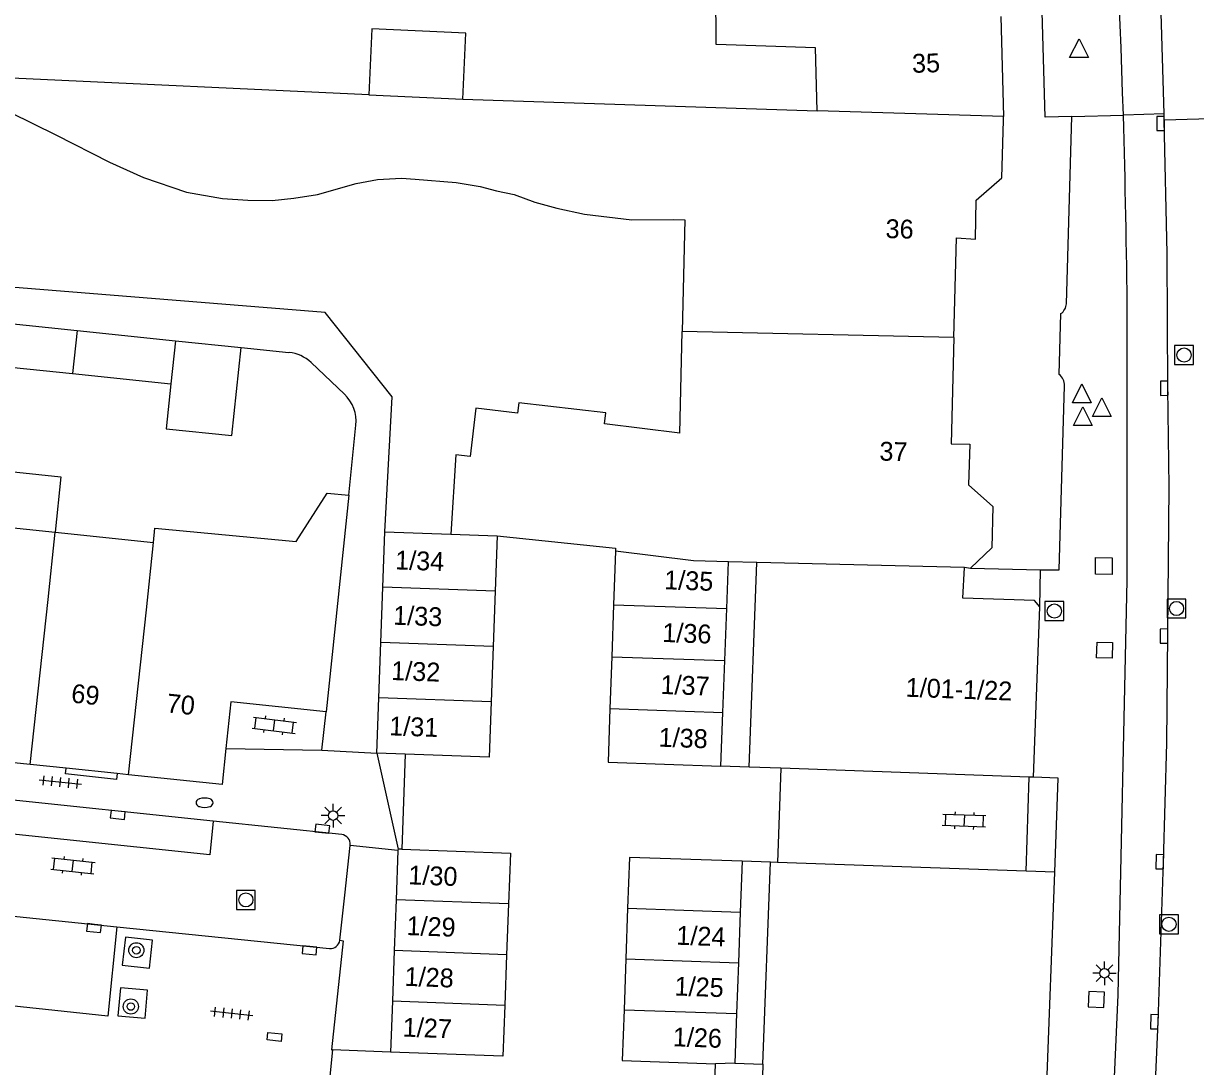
# Model space of a CAD drawing. Extents: x 132998 to 136004, y 396998 to 398512.
# Drawn here: x 133481.2 to 133543.5, y 397360.2 to 397415.5 of the extents above; entities that cross this region are included whole.
import ezdxf

# ---------------------------------------------------------------- set-up
doc = ezdxf.new("R2010")
doc.units = 0
for name, color, linetype in [('gg-afsc-erfafscheiding', 7, 'Continuous'), ('gg-afsc-hekwerk', 7, 'Continuous'), ('gg-afsc-muur', 7, 'Continuous'), ('gg-anno-huisnummerreeks BGT', 7, 'Continuous'), ('gg-bbg-bijgebouw', 7, 'Continuous'), ('gg-bbg-gedigitaliseerde bebouwing', 7, 'Continuous'), ('gg-bbg-gedigitaliseerde bijgebouw', 7, 'Continuous'), ('gg-bbg-hoofdgebouw', 7, 'Continuous'), ('gg-bbg-luifel en loopbrug', 7, 'Continuous'), ('gg-bbg-onder overbouw', 7, 'Continuous'), ('gg-bbg-pand overbouw', 7, 'Continuous'), ('gg-bbg-tussenscheiding', 7, 'Continuous'), ('gg-knt-verharding', 7, 'Continuous'), ('gg-knt-verharding nz', 7, 'Continuous'), ('gt-grn-weggrens', 7, 'Continuous'), ('gt-symb-boom', 7, 'Continuous'), ('gt-symb-brandkraan', 7, 'Continuous'), ('gt-symb-klinker verharding', 7, 'Continuous'), ('gt-symb-kolk', 7, 'Continuous'), ('gt-symb-kolk center center', 7, 'Continuous'), ('gt-symb-lichtmast', 7, 'Continuous'), ('gt-symb-rioolschacht', 7, 'Continuous'), ('gt-symb-tegel verharding', 7, 'Continuous'), ('gt-symb-waterafsluiter', 7, 'Continuous')]:
    doc.layers.add(name, color=color, linetype=linetype)

# ---------------------------------------------------------------- blocks, each defined once
blk = doc.blocks.new('gt0-KOLK')
at = {"layer": 'gt-symb-kolk'}
blk.add_lwpolyline([(0, 0), (0.375, 0), (0.375, 0.4), (-0.375, 0.4), (-0.375, 0), (0, 0)], dxfattribs=at)
blk = doc.blocks.new('gt0-WAFSL')
at = {"layer": 'gt-symb-waterafsluiter'}
for p, q in [((-0.5, -0.333), (0, 0.667)), ((0, 0.667), (0.5, -0.333)), ((0.5, -0.333), (-0.5, -0.333))]:
    blk.add_line(p, q, dxfattribs=at)
blk = doc.blocks.new('gt0-RS')
at = {"layer": 'gt-symb-rioolschacht'}
blk.add_lwpolyline([(-0.5, -0.5), (0.5, -0.5), (0.5, 0.5), (-0.5, 0.5)], close=True, dxfattribs=at)
blk.add_circle((0, 0), 0.375, dxfattribs=at)
blk = doc.blocks.new('gt0-TEG1')
at = {"layer": 'gt-symb-tegel verharding'}
for p, q in [((-1.125, 0), (1.125, 0)), ((-0.9, -0.25), (-0.9, 0.25)), ((-0.45, -0.25), (-0.45, 0.25)), ((0, -0.25), (0, 0.25)), ((0.45, -0.25), (0.45, 0.25)), ((0.9, -0.25), (0.9, 0.25))]:
    blk.add_line(p, q, dxfattribs=at)
blk = doc.blocks.new('gt0-KL1')
at = {"layer": 'gt-symb-klinker verharding'}
for p, q in [((-1.15, 0.3), (1.15, 0.3)), ((-1, -0.3), (-1, 0.3)), ((-0.5, 0.3), (-0.5, 0.45)), ((0, -0.3), (0, 0.3)), ((0.5, 0.3), (0.5, 0.45)), ((1, -0.3), (1, 0.3)), ((-1.15, -0.3), (1.15, -0.3)), ((-0.5, -0.45), (-0.5, -0.3)), ((0.5, -0.45), (0.5, -0.3))]:
    blk.add_line(p, q, dxfattribs=at)
blk = doc.blocks.new('gt0-LMAST')
at = {"layer": 'gt-symb-lichtmast'}
for p, q in [((-0.182, 0.173), (-0.447, 0.438)), ((-0.005, 0.246), (-0.005, 0.621)), ((0.172, 0.173), (0.437, 0.438)), ((-0.255, -0.004), (-0.63, -0.004)), ((-0.182, -0.181), (-0.447, -0.446)), ((-0.005, -0.254), (-0.005, -0.629)), ((0.437, -0.446), (0.172, -0.181)), ((0.245, -0.004), (0.62, -0.004))]:
    blk.add_line(p, q, dxfattribs=at)
blk.add_circle((-0.005, -0.004), 0.25, dxfattribs=at)
blk = doc.blocks.new('gt0-BOOM')
at = {"layer": 'gt-symb-boom'}
for radius in [0.4, 0.2]:
    blk.add_circle((0, 0), radius, dxfattribs=at)
blk = doc.blocks.new('gt0-BR')
at = {"layer": 'gt-symb-brandkraan'}
for centre, radius, start, end in [((-0.244, 0), 0.206, 107.56694, 252.43307), ((0.599, -2.664), 3, 106.89205, 107.56694), ((0, -0.691), 0.938, 73.10799, 106.89205), ((-0.599, -2.664), 3, 72.43309, 73.10799), ((0.244, 0), 0.206, 287.56695, 72.43309), ((0.599, 2.664), 3, 252.43307, 253.10797), ((0, 0.691), 0.938, 253.10797, 286.89206), ((-0.599, 2.664), 3, 286.89206, 287.56695)]:
    blk.add_arc(centre, radius, start, end, dxfattribs=at)
blk = doc.blocks.new('gt0-KOLKCC')
at = {"layer": 'gt-symb-kolk center center'}
blk.add_lwpolyline([(-0.375, 0.2), (0.375, 0.2), (0.375, -0.2), (-0.375, -0.2)], close=True, dxfattribs=at)

msp = doc.modelspace()

# ---------------------------------------------------------------- linework, layer by layer
at = {"layer": 'gg-afsc-erfafscheiding'}
for p, q in [((133492.798, 397398.327), (133495.342, 397398.064)), ((133496.512, 397397.527), (133498.279, 397395.853)), ((133498.509, 397390.484), (133498.893, 397394.195))]:
    msp.add_line(p, q, dxfattribs=at)
msp.add_lwpolyline([(133500.42, 397388.55), (133500.823, 397395.703), (133497.267, 397400.181), (133454.225, 397403.644), (133455.323, 397421.968), (133456.396, 397429.5), (133457.85, 397437.75)], dxfattribs=at)
for centre, radius, start, end in [((133495.138, 397396.076), 1.999, 46.56082, 84.13136), ((133496.901, 397394.4), 2.003, 354.12984, 46.51193)]:
    msp.add_arc(centre, radius, start, end, dxfattribs=at)
at = {"layer": 'gg-afsc-hekwerk'}
for p, q in [((133500, 397376.8), (133501.13, 397371.71)), ((133519.765, 397376.058), (133518.263, 397376.103)), ((133520.893, 397371.013), (133519.391, 397371.068))]:
    msp.add_line(p, q, dxfattribs=at)
at = {"layer": 'gg-afsc-muur'}
for p, q in [((133497.65, 397361.05), (133497.362, 397358.239)), ((133500.73, 397360.93), (133497.65, 397361.05))]:
    msp.add_line(p, q, dxfattribs=at)
at = {"layer": 'gg-bbg-bijgebouw'}
for p, q in [((133500.315, 397385.602), (133500.42, 397388.55)), ((133506.39, 397388.33), (133506.285, 397385.395)), ((133512.672, 397387.513), (133512.571, 397384.677)), ((133500.21, 397382.667), (133500.315, 397385.602)), ((133506.285, 397385.395), (133506.18, 397382.46)), ((133512.571, 397384.677), (133512.474, 397381.919)), ((133500.105, 397379.732), (133500.21, 397382.667)), ((133506.18, 397382.46), (133506.075, 397379.525)), ((133512.474, 397381.919), (133512.376, 397379.161)), ((133500, 397376.8), (133500.105, 397379.732)), ((133501.506, 397376.747), (133500, 397376.8)), ((133501.127, 397371.63), (133501.03, 397369.017)), ((133501.13, 397371.71), (133501.127, 397371.63)), ((133501.33, 397371.703), (133501.13, 397371.71)), ((133501.03, 397369.017), (133500.93, 397366.325)), ((133506.99, 397368.798), (133506.89, 397366.105)), ((133513.312, 397368.577), (133513.218, 397365.883)), ((133500.93, 397366.325), (133500.83, 397363.632)), ((133506.89, 397366.105), (133506.79, 397363.413)), ((133513.218, 397365.883), (133513.124, 397363.189)), ((133500.83, 397363.632), (133500.73, 397360.93)), ((133517.843, 397356.426), (133517.978, 397360.323))]:
    msp.add_line(p, q, dxfattribs=at)
for points in [[(133506.075, 397379.525), (133505.97, 397376.59), (133501.506, 397376.747)], [(133512.376, 397379.161), (133512.275, 397376.324), (133518.263, 397376.103)], [(133501.33, 397371.703), (133507.09, 397371.49), (133506.99, 397368.798)], [(133519.391, 397371.068), (133513.405, 397371.271), (133513.312, 397368.577)], [(133506.79, 397363.413), (133506.69, 397360.72), (133500.73, 397360.93)], [(133513.124, 397363.189), (133513.031, 397360.495), (133517.978, 397360.323)]]:
    msp.add_lwpolyline(points, dxfattribs=at)
at = {"layer": 'gg-bbg-gedigitaliseerde bebouwing'}
for p, q in [((133504.57, 397411.507), (133523.367, 397410.88)), ((133516.077, 397393.782), (133516.211, 397399.18)), ((133498.509, 397390.484), (133497.32, 397378.99)), ((133477.89, 397389.047), (133482.929, 397388.526)), ((133482.929, 397388.526), (133488.15, 397387.986)), ((133520.166, 397386.918), (133518.664, 397386.955)), ((133519.765, 397376.058), (133520.166, 397386.918)), ((133520.496, 397360.29), (133520.893, 397371.013))]:
    msp.add_line(p, q, dxfattribs=at)
for points in [[(133523.367, 397410.88), (133523.286, 397414.223), (133518.008, 397414.406), (133517.993, 397417.308), (133523.438, 397417.532)], [(133499.575, 397411.74), (133480.641, 397412.623)], [(133480.556, 397410.786), (133482.967, 397409.607), (133485.824, 397408.155), (133487.628, 397407.341), (133489.907, 397406.568), (133491.813, 397406.224), (133493.15, 397406.14), (133494.445, 397406.131), (133495.595, 397406.25), (133496.848, 397406.436), (133498.906, 397407.019), (133500.036, 397407.247), (133501.314, 397407.301), (133502.04, 397407.261), (133504.206, 397407.073), (133505.491, 397406.869), (133506.362, 397406.642), (133507.299, 397406.441), (133508.385, 397406.039), (133509.563, 397405.718), (133511.024, 397405.397), (133513.529, 397405.102), (133515.732, 397405.109), (133516.357, 397405.094), (133516.211, 397399.18)], [(133516.077, 397393.782), (133512.08, 397394.271), (133512.157, 397394.859), (133507.54, 397395.382), (133507.475, 397394.834), (133505.251, 397395.106), (133504.962, 397392.545), (133504.196, 397392.632), (133503.933, 397388.421)], [(133488.15, 397387.986), (133488.227, 397388.73), (133495.731, 397388.038), (133497.36, 397390.588), (133498.509, 397390.484)]]:
    msp.add_lwpolyline(points, dxfattribs=at)
at = {"layer": 'gg-bbg-gedigitaliseerde bijgebouw'}
for p, q in [((133479.048, 397399.749), (133484.105, 397399.226)), ((133484.105, 397399.226), (133489.325, 397398.686)), ((133489.325, 397398.686), (133492.798, 397398.327)), ((133478.796, 397397.463), (133483.853, 397396.94)), ((133483.853, 397396.94), (133489.073, 397396.4)), ((133500.42, 397388.55), (133503.933, 397388.421)), ((133518.572, 397384.468), (133518.664, 397386.955)), ((133518.47, 397381.711), (133518.572, 397384.468)), ((133518.368, 397378.953), (133518.47, 397381.711)), ((133518.263, 397376.103), (133518.368, 397378.953)), ((133519.391, 397371.068), (133519.292, 397368.369)), ((133519.292, 397368.369), (133519.193, 397365.676)), ((133519.193, 397365.676), (133519.095, 397362.982)), ((133519.095, 397362.982), (133518.998, 397360.345)), ((133518.998, 397360.345), (133520.496, 397360.29))]:
    msp.add_line(p, q, dxfattribs=at)
for points in [[(133504.57, 397411.507), (133504.733, 397415.003), (133499.738, 397415.236), (133499.575, 397411.74)], [(133489.073, 397396.4), (133488.827, 397394.016), (133492.316, 397393.656), (133492.798, 397398.327)]]:
    msp.add_lwpolyline(points, dxfattribs=at)
at = {"layer": 'gg-bbg-hoofdgebouw'}
for p, q in [((133533.125, 397415.891), (133533.255, 397410.574)), ((133534.86, 397375.52), (133535.19, 397384.57)), ((133481.608, 397376.194), (133476.551, 397376.717)), ((133483.511, 397375.997), (133481.608, 397376.194)), ((133486.224, 397375.717), (133483.511, 397375.997)), ((133486.829, 397375.654), (133486.224, 397375.717)), ((133521.451, 397375.998), (133519.765, 397376.058)), ((133534.86, 397375.52), (133534.633, 397375.528)), ((133521.274, 397371), (133520.893, 397371.013)), ((133535.98, 397370.48), (133534.467, 397370.533)), ((133535.533, 397358.556), (133535.98, 397370.48))]:
    msp.add_line(p, q, dxfattribs=at)
for points in [[(133530.629, 397398.855), (133530.76, 397404.14), (133531.77, 397404.07), (133531.82, 397406.15), (133533.18, 397407.32), (133533.26, 397410.38), (133533.255, 397410.574)], [(133530.629, 397398.855), (133530.49, 397393.21), (133531.47, 397393.19), (133531.41, 397391.03), (133532.69, 397389.88), (133532.64, 397387.7), (133531.51, 397386.62)], [(133506.39, 397388.33), (133512.678, 397387.671), (133512.672, 397387.513)], [(133535.19, 397384.57), (133534.9, 397384.9), (133531.1, 397385.03), (133531.189, 397386.644)], [(133531.189, 397386.644), (133531.19, 397386.66), (133531.51, 397386.62)], [(133497.32, 397378.99), (133492.25, 397379.53), (133491.996, 397377.049)], [(133491.996, 397377.049), (133491.8, 397375.14), (133486.829, 397375.654)]]:
    msp.add_lwpolyline(points, dxfattribs=at)
at = {"layer": 'gg-bbg-luifel en loopbrug'}
msp.add_lwpolyline([(133477.89, 397389.047), (133478.209, 397391.984), (133483.241, 397391.464), (133482.929, 397388.526)], dxfattribs=at)
at = {"layer": 'gg-bbg-onder overbouw'}
for p, q in [((133534.633, 397375.528), (133521.451, 397375.998)), ((133534.467, 397370.533), (133521.274, 397371))]:
    msp.add_line(p, q, dxfattribs=at)
at = {"layer": 'gg-bbg-pand overbouw'}
for p, q in [((133521.451, 397375.998), (133521.274, 397371)), ((133534.467, 397370.533), (133534.633, 397375.528))]:
    msp.add_line(p, q, dxfattribs=at)
at = {"layer": 'gg-bbg-tussenscheiding'}
for p, q in [((133499.575, 397411.74), (133504.57, 397411.507)), ((133533.255, 397410.574), (133523.367, 397410.88)), ((133484.105, 397399.226), (133483.853, 397396.94)), ((133489.325, 397398.686), (133489.073, 397396.4)), ((133530.629, 397398.855), (133516.211, 397399.18)), ((133503.933, 397388.421), (133506.39, 397388.33)), ((133531.189, 397386.644), (133520.166, 397386.918)), ((133506.285, 397385.395), (133500.315, 397385.602)), ((133512.571, 397384.677), (133518.572, 397384.468)), ((133506.18, 397382.46), (133500.21, 397382.667)), ((133512.474, 397381.919), (133518.47, 397381.711)), ((133506.075, 397379.525), (133500.105, 397379.732)), ((133512.376, 397379.161), (133518.368, 397378.953)), ((133506.99, 397368.798), (133501.03, 397369.017)), ((133513.312, 397368.577), (133519.292, 397368.369)), ((133506.89, 397366.105), (133500.93, 397366.325)), ((133513.218, 397365.883), (133519.193, 397365.676)), ((133506.79, 397363.413), (133500.83, 397363.632)), ((133513.124, 397363.189), (133519.095, 397362.982)), ((133518.998, 397360.345), (133517.978, 397360.323)), ((133520.496, 397360.29), (133520.475, 397359.636))]:
    msp.add_line(p, q, dxfattribs=at)
for points in [[(133481.608, 397376.194), (133482.559, 397384.952), (133482.929, 397388.526)], [(133486.829, 397375.654), (133487.78, 397384.411), (133488.15, 397387.986)], [(133518.664, 397386.955), (133516.808, 397387.001), (133512.672, 397387.513)]]:
    msp.add_lwpolyline(points, dxfattribs=at)
at = {"layer": 'gg-knt-verharding'}
for p, q in [((133536.597, 397400.645), (133536.882, 397410.578)), ((133541.794, 397410.38), (133541.784, 397410.723)), ((133536.222, 397396.894), (133536.309, 397400.122)), ((133531.51, 397386.62), (133535.233, 397386.53)), ((133535.19, 397384.57), (133535.233, 397386.53)), ((133497.09, 397376.95), (133497.32, 397378.99)), ((133491.996, 397377.049), (133497.09, 397376.95)), ((133501.506, 397376.747), (133501.33, 397371.703)), ((133491.323, 397373.192), (133467.732, 397375.656)), ((133498.14, 397372.48), (133491.323, 397373.192)), ((133498.587, 397371.901), (133498.59, 397371.93)), ((133498.3, 397369.263), (133498.587, 397371.901)), ((133501.127, 397371.63), (133498.587, 397371.901)), ((133498.039, 397366.869), (133498.3, 397369.263)), ((133486.21, 397367.592), (133497.49, 397366.43))]:
    msp.add_line(p, q, dxfattribs=at)
for points in [[(133541.784, 397410.723), (133541.463, 397421.436), (133541.237, 397427.441), (133541.095, 397429.672), (133540.518, 397439.166)], [(133536.882, 397410.578), (133535.478, 397410.539), (133534.94, 397429.23)], [(133532.558, 397232.32), (133532.862, 397236.522), (133533.753, 397247.986), (133534.86, 397262.429), (133535.57, 397271.878), (133536.358, 397283.352), (133537.375, 397297.775), (133538.184, 397309.639), (133539.189, 397324.122), (133539.96, 397335.612), (133540.386, 397341.823), (133540.777, 397348.022), (133541.159, 397355.302), (133541.471, 397362.544), (133541.757, 397371.03), (133541.926, 397377.322), (133542.057, 397390.929), (133541.991, 397396.162), (133541.942, 397403.319), (133541.794, 397410.38)], [(133539.103, 397358.429), (133539.343, 397363.98), (133539.821, 397385.971), (133539.833, 397399.978)], [(133535.233, 397386.53), (133536.219, 397386.531), (133536.508, 397396.299)], [(133538.138, 397387.173), (133539.029, 397387.157), (133539.03, 397386.279), (133538.139, 397386.295), (133538.138, 397387.173)], [(133539.053, 397382.665), (133539.03, 397381.845), (133538.206, 397381.862), (133538.229, 397382.682), (133539.053, 397382.665)], [(133486.224, 397375.717), (133486.192, 397375.407), (133483.48, 397375.698), (133483.511, 397375.997)], [(133486.21, 397367.592), (133485.726, 397362.851), (133478.268, 397363.645), (133478.777, 397368.358)], [(133486.496, 397365.549), (133487.931, 397365.386), (133488.1, 397366.877), (133486.659, 397367.04), (133486.496, 397365.549)], [(133498.039, 397366.869), (133498.221, 397366.849), (133497.596, 397361.052), (133497.65, 397361.05)], [(133486.393, 397364.351), (133486.264, 397362.854), (133487.711, 397362.73), (133487.84, 397364.227), (133486.393, 397364.351)], [(133537.759, 397363.331), (133538.588, 397363.297), (133538.614, 397364.114), (133537.786, 397364.147), (133537.759, 397363.331)]]:
    msp.add_lwpolyline(points, dxfattribs=at)
for centre, radius, start, end in [((133033.496, 397395.326), 506.359, 1.73492, 6.05306), ((133010.898, 397394.917), 528.959, 0.54824, 1.7051), ((133535.916, 397400.679), 0.682, 305.19951, 357.12004), ((133535.767, 397396.309), 0.741, 359.2227, 52.12191), ((133498.076, 397371.969), 0.515, 355.68659, 82.89223), ((133497.53, 397366.943), 0.515, 265.55873, 351.73543)]:
    msp.add_arc(centre, radius, start, end, dxfattribs=at)
at = {"layer": 'gg-knt-verharding nz'}
msp.add_line((133478.777, 397368.358), (133486.21, 397367.592), dxfattribs=at)
msp.add_lwpolyline([(133491.323, 397373.192), (133491.136, 397371.402), (133467.533, 397373.883)], dxfattribs=at)
at = {"layer": 'gt-grn-weggrens'}
for p, q in [((133536.882, 397410.578), (133539.623, 397410.656)), ((133541.784, 397410.723), (133539.623, 397410.656)), ((133544.901, 397410.469), (133541.794, 397410.38)), ((133497.09, 397376.95), (133500, 397376.8))]:
    msp.add_line(p, q, dxfattribs=at)
msp.add_lwpolyline([(133535.98, 397370.48), (133536.159, 397375.473), (133534.86, 397375.52)], dxfattribs=at)

# ---------------------------------------------------------------- block references
at = {"layer": 'gt-symb-boom'}
for p in [(133487.242, 397366.343), (133486.949, 397363.356)]:
    msp.add_blockref('gt0-BOOM', p, dxfattribs=at)
at = {"layer": 'gt-symb-brandkraan'}
msp.add_blockref('gt0-BR', (133490.862, 397374.171), dxfattribs=at)
at = {"layer": 'gt-symb-klinker verharding'}
for p, rotation in [((133494.56, 397378.276), -7.125016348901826), ((133531.173, 397373.212), 177.9361802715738), ((133483.872, 397370.822), -5.967037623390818)]:
    msp.add_blockref('gt0-KL1', p, dxfattribs=dict(at, rotation=rotation))
at = {"layer": 'gt-symb-kolk'}
for p, rotation in [((133541.799, 397410.214), 91.18642938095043), ((133541.991, 397396.162), 90.39541529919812), ((133541.978, 397383.013), 90.39541529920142), ((133486.271, 397373.72), 174.14690870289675), ((133497.09, 397372.59), -5.910070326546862), ((133541.757, 397371.03), 88.45838341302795), ((133485.015, 397367.715), 174.0329623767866), ((133496.453, 397366.537), 174.08992967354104), ((133541.471, 397362.544), 88.45838341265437)]:
    msp.add_blockref('gt0-KOLK', p, dxfattribs=dict(at, rotation=rotation))
at = {"layer": 'gt-symb-kolk center center', "rotation": -5.9100703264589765}
msp.add_blockref('gt0-KOLKCC', (133494.576, 397361.743), dxfattribs=at)
at = {"layer": 'gt-symb-lichtmast'}
for p in [(133497.688, 397373.489), (133538.626, 397365.122)]:
    msp.add_blockref('gt0-LMAST', p, dxfattribs=at)
at = {"layer": 'gt-symb-rioolschacht'}
for p in [(133542.842, 397397.924), (133542.445, 397384.476), (133535.963, 397384.341), (133493.052, 397369.013), (133542.044, 397367.719)]:
    msp.add_blockref('gt0-RS', p, dxfattribs=at)
at = {"layer": 'gt-symb-tegel verharding'}
for p, rotation in [((133483.21, 397375.262), -5.910070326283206), ((133492.299, 397362.98), 173.6851155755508)]:
    msp.add_blockref('gt0-TEG1', p, dxfattribs=dict(at, rotation=rotation))
at = {"layer": 'gt-symb-waterafsluiter'}
for p in [(133537.273, 397414.043), (133537.42, 397395.726), (133538.477, 397394.994), (133537.47, 397394.513)]:
    msp.add_blockref('gt0-WAFSL', p, dxfattribs=at)

# ---------------------------------------------------------------- texts
at = {"layer": 'gg-anno-huisnummerreeks BGT'}
for s, rotation, p in [('35', 1.4, (133528.419, 397412.898)), ('36', 358.6, (133526.993, 397404.134)), ('37', 358.4, (133526.667, 397392.328)), ('1/34', 358, (133500.963, 397386.553)), ('1/35', 358, (133515.242, 397385.5)), ('1/33', 358, (133500.858, 397383.618)), ('1/36', 358, (133515.143, 397382.704)), ('1/32', 358, (133500.753, 397380.683)), ('1/37', 358, (133515.045, 397379.945)), ('1/01-1/22', 357.9, (133528.06, 397379.797)), ('69', 354.1, (133483.752, 397379.491)), ('70', 354.1, (133488.812, 397378.968)), ('1/31', 358, (133500.648, 397377.748)), ('1/38', 358, (133514.946, 397377.147)), ('1/30', 357.9, (133501.665, 397369.842)), ('1/29', 357.9, (133501.565, 397367.15)), ('1/24', 358, (133515.887, 397366.638)), ('1/28', 357.9, (133501.465, 397364.457)), ('1/25', 358, (133515.793, 397363.944)), ('1/27', 357.9, (133501.365, 397361.765)), ('1/26', 358, (133515.699, 397361.251))]:
    msp.add_text(s, height=1, rotation=rotation, dxfattribs=at).set_placement(p)

doc.saveas('drawing.dxf')
